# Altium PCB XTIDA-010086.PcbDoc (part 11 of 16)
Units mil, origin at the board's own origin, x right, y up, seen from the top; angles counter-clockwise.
Board outline 14763.78 x 8267.72 mil, 6 copper layers (Top Layer, GND Layer, Signal Layer 1, Signal Layer 2, Power Layer, Bottom Layer), stack 62 mil thick; 1933 components, 1002 nets, 4886 pads, 6482 vias.
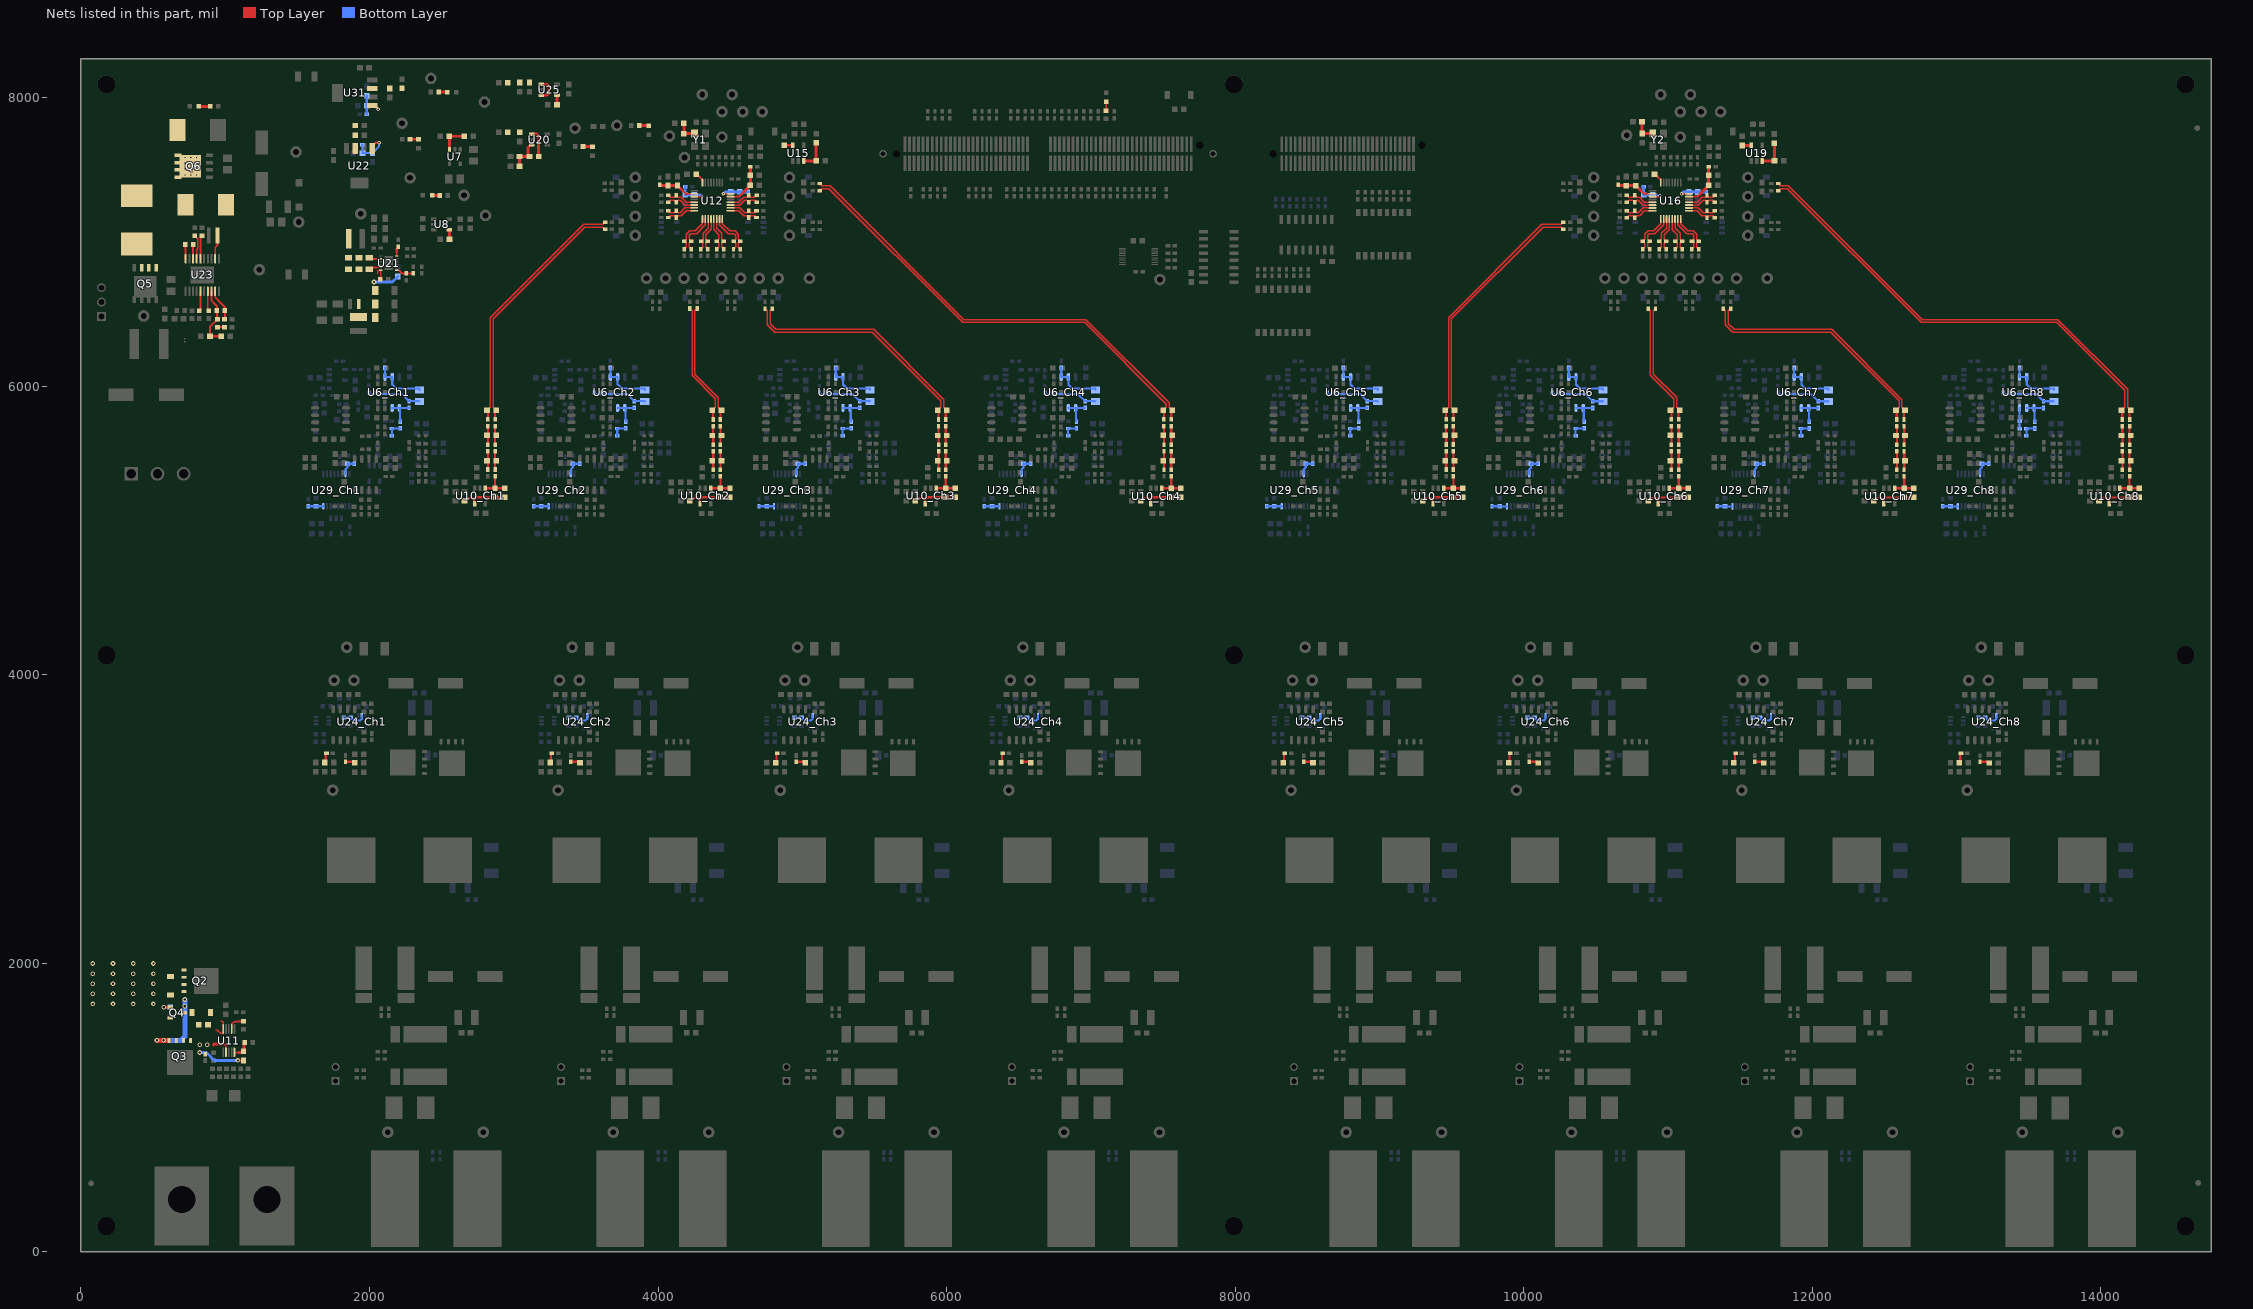
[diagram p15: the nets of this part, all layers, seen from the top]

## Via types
v1: diameter 32, hole 16, Top Layer to Bottom Layer, tented both sides, 4685 vias
v2: diameter 24, hole 12, Top Layer to Bottom Layer, tented both sides, 1013 vias
v3: diameter 32, hole 16, Top Layer to Bottom Layer, 728 vias
v4: diameter 19.68, hole 7.87, Top Layer to Bottom Layer, 40 vias
v5: diameter 214.57, hole 140, Top Layer to Bottom Layer, 16 vias

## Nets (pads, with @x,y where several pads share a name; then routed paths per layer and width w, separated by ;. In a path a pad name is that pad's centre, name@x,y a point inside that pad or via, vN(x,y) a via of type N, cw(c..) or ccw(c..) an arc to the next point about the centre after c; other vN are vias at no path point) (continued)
NetC38_Ch8_1: C38_Ch8.1 R53_Ch8.2 U6_Ch8.3 | length 142.9
  Bottom Layer w15: U6_Ch8.3@13435.7,5848.21 13436.08,5847.83 C38_Ch8.1@13436.08,5755.5 R53_Ch8.2@13436.08,5705.5
NetC41_Ch1_1: C41_Ch1.1 R50_Ch1.1 U6_Ch1.1 U6_Ch1.2 | length 213.7
  Bottom Layer w15: U6_Ch1.2@2158,5848.76 U6_Ch1.1@2208,5848.76 ; C41_Ch1.1@2214,5753.67 2211.79,5755.88 2211.79,5844.98 U6_Ch1.1@2208,5848.76 ; R50_Ch1.1@2274,5848.43 2273.66,5848.76 U6_Ch1.1@2208,5848.76
NetC41_Ch1_2: C41_Ch1.2 R52_Ch1.2 R53_Ch1.1 | length 108.5
  Bottom Layer w15: R52_Ch1.2@2155.62,5656.05 R53_Ch1.1@2155.62,5706.05 2213.62,5706.05 C41_Ch1.2@2214,5706.43
NetC41_Ch2_1: C41_Ch2.1 R50_Ch2.1 U6_Ch2.1 U6_Ch2.2 | length 213.7
  Bottom Layer w15: U6_Ch2.2@3720,5848.68 U6_Ch2.1@3770,5848.68 ; C41_Ch2.1@3776,5753.59 3773.79,5755.8 3773.79,5844.9 U6_Ch2.1@3770,5848.68 ; R50_Ch2.1@3836,5848.35 3835.66,5848.68 U6_Ch2.1@3770,5848.68
NetC41_Ch2_2: C41_Ch2.2 R52_Ch2.2 R53_Ch2.1 | length 108.5
  Bottom Layer w15: R52_Ch2.2@3717.62,5655.97 R53_Ch2.1@3717.62,5705.97 3775.62,5705.97 C41_Ch2.2@3776,5706.35
NetC41_Ch3_1: C41_Ch3.1 R50_Ch3.1 U6_Ch3.1 U6_Ch3.2 | length 213.7
  Bottom Layer w15: U6_Ch3.2@5282,5848.61 U6_Ch3.1@5332,5848.61 ; C41_Ch3.1@5338,5753.51 5335.79,5755.72 5335.79,5844.82 U6_Ch3.1@5332,5848.61 ; R50_Ch3.1@5398,5848.27 5397.66,5848.61 U6_Ch3.1@5332,5848.61
NetC41_Ch3_2: C41_Ch3.2 R52_Ch3.2 R53_Ch3.1 | length 108.5
  Bottom Layer w15: R52_Ch3.2@5279.62,5655.89 R53_Ch3.1@5279.62,5705.89 5337.62,5705.89 C41_Ch3.2@5338,5706.27
NetC41_Ch4_1: C41_Ch4.1 R50_Ch4.1 U6_Ch4.1 U6_Ch4.2 | length 213.7
  Bottom Layer w15: U6_Ch4.2@6844,5848.53 U6_Ch4.1@6894,5848.53 ; C41_Ch4.1@6900,5753.43 6897.79,5755.65 6897.79,5844.74 U6_Ch4.1@6894,5848.53 ; R50_Ch4.1@6960,5848.19 6959.66,5848.53 U6_Ch4.1@6894,5848.53
NetC41_Ch4_2: C41_Ch4.2 R52_Ch4.2 R53_Ch4.1 | length 108.5
  Bottom Layer w15: R52_Ch4.2@6841.62,5655.81 R53_Ch4.1@6841.62,5705.81 6899.62,5705.81 C41_Ch4.2@6900,5706.19
NetC41_Ch5_1: C41_Ch5.1 R50_Ch5.1 U6_Ch5.1 U6_Ch5.2 | length 213.7
  Bottom Layer w15: U6_Ch5.2@8799.7,5848.45 U6_Ch5.1@8849.7,5848.45 ; C41_Ch5.1@8855.7,5753.35 8853.49,5755.57 8853.49,5844.66 U6_Ch5.1@8849.7,5848.45 ; R50_Ch5.1@8915.7,5848.11 8915.36,5848.45 U6_Ch5.1@8849.7,5848.45
NetC41_Ch5_2: C41_Ch5.2 R52_Ch5.2 R53_Ch5.1 | length 108.5
  Bottom Layer w15: R52_Ch5.2@8797.32,5655.73 R53_Ch5.1@8797.32,5705.73 8855.32,5705.73 C41_Ch5.2@8855.7,5706.11
NetC41_Ch6_1: C41_Ch6.1 R50_Ch6.1 U6_Ch6.1 U6_Ch6.2 | length 213.7
  Bottom Layer w15: U6_Ch6.2@10361.7,5848.37 U6_Ch6.1@10411.7,5848.37 ; C41_Ch6.1@10417.7,5753.28 10415.49,5755.49 10415.49,5844.58 U6_Ch6.1@10411.7,5848.37 ; R50_Ch6.1@10477.7,5848.03 10477.36,5848.37 U6_Ch6.1@10411.7,5848.37
NetC41_Ch6_2: C41_Ch6.2 R52_Ch6.2 R53_Ch6.1 | length 108.5
  Bottom Layer w15: R52_Ch6.2@10359.32,5655.65 R53_Ch6.1@10359.32,5705.65 10417.32,5705.65 C41_Ch6.2@10417.7,5706.03
NetC41_Ch7_1: C41_Ch7.1 R50_Ch7.1 U6_Ch7.1 U6_Ch7.2 | length 213.7
  Bottom Layer w15: U6_Ch7.2@11923.7,5848.29 U6_Ch7.1@11973.7,5848.29 ; C41_Ch7.1@11979.7,5753.2 11977.49,5755.41 11977.49,5844.5 U6_Ch7.1@11973.7,5848.29 ; R50_Ch7.1@12039.7,5847.95 12039.36,5848.29 U6_Ch7.1@11973.7,5848.29
NetC41_Ch7_2: C41_Ch7.2 R52_Ch7.2 R53_Ch7.1 | length 108.5
  Bottom Layer w15: R52_Ch7.2@11921.32,5655.57 R53_Ch7.1@11921.32,5705.57 11979.32,5705.57 C41_Ch7.2@11979.7,5705.95
NetC41_Ch8_1: C41_Ch8.1 R50_Ch8.1 U6_Ch8.1 U6_Ch8.2 | length 213.7
  Bottom Layer w15: U6_Ch8.2@13485.7,5848.21 U6_Ch8.1@13535.7,5848.21 ; C41_Ch8.1@13541.7,5753.12 13539.49,5755.33 13539.49,5844.43 U6_Ch8.1@13535.7,5848.21 ; R50_Ch8.1@13601.7,5847.87 13601.36,5848.21 U6_Ch8.1@13535.7,5848.21
NetC41_Ch8_2: C41_Ch8.2 R52_Ch8.2 R53_Ch8.1 | length 108.5
  Bottom Layer w15: R52_Ch8.2@13483.32,5655.5 R53_Ch8.1@13483.32,5705.5 13541.32,5705.5 C41_Ch8.2@13541.7,5705.87
NetC42_Ch1_1: C42_Ch1.1 R186_Ch1.1 U6_Ch1.6 U6_Ch1.7 | length 376.8
  Bottom Layer w15: R186_Ch1.1@2107,6127.76 2108,6126.76 U6_Ch1.6@2108,6063.33 U6_Ch1.7@2158,6063.33 2158,6011.49 2185.79,5983.7 2346,5983.7 C42_Ch1.1@2346,5973.05
NetC42_Ch1_2: C42_Ch1.2 R50_Ch1.2 R51_Ch1.1 | length 375.9
  Bottom Layer w15: R51_Ch1.1@1995,5953.05 2002.35,5945.7 2223.97,5945.7 R50_Ch1.2@2274,5895.67 2343.38,5895.67 C42_Ch1.2@2346,5893.05
NetC42_Ch2_1: C42_Ch2.1 R186_Ch2.1 U6_Ch2.6 U6_Ch2.7 | length 375.4
  Bottom Layer w15: R186_Ch2.1@3670,6126.68 U6_Ch2.6@3670,6063.25 U6_Ch2.7@3720,6063.25 3720,6011.41 3747.79,5983.62 3908,5983.62 C42_Ch2.1@3908,5972.97
NetC42_Ch2_2: C42_Ch2.2 R50_Ch2.2 R51_Ch2.1 | length 375.9
  Bottom Layer w15: R51_Ch2.1@3557,5952.97 3564.35,5945.62 3785.97,5945.62 R50_Ch2.2@3836,5895.59 3905.38,5895.59 C42_Ch2.2@3908,5892.97
NetC42_Ch3_1: C42_Ch3.1 R186_Ch3.1 U6_Ch3.6 U6_Ch3.7 | length 375.4
  Bottom Layer w15: R186_Ch3.1@5232,6126.6 U6_Ch3.6@5232,6063.17 U6_Ch3.7@5282,6063.17 5282,6011.33 5309.79,5983.54 5470,5983.54 C42_Ch3.1@5470,5972.89
NetC42_Ch3_2: C42_Ch3.2 R50_Ch3.2 R51_Ch3.1 | length 375.9
  Bottom Layer w15: R51_Ch3.1@5119,5952.89 5126.35,5945.54 5347.97,5945.54 R50_Ch3.2@5398,5895.51 5467.38,5895.51 C42_Ch3.2@5470,5892.89
NetC42_Ch4_1: C42_Ch4.1 R186_Ch4.1 U6_Ch4.6 U6_Ch4.7 | length 375.4
  Bottom Layer w15: R186_Ch4.1@6794,6126.52 U6_Ch4.6@6794,6063.09 U6_Ch4.7@6844,6063.09 6844,6011.25 6871.79,5983.46 7032,5983.46 C42_Ch4.1@7032,5972.81
NetC42_Ch4_2: C42_Ch4.2 R50_Ch4.2 R51_Ch4.1 | length 375.9
  Bottom Layer w15: R51_Ch4.1@6681,5952.81 6688.35,5945.46 6909.97,5945.46 R50_Ch4.2@6960,5895.43 7029.38,5895.43 C42_Ch4.2@7032,5892.81
NetC42_Ch5_1: C42_Ch5.1 R186_Ch5.1 U6_Ch5.6 U6_Ch5.7 | length 375.4
  Bottom Layer w15: R186_Ch5.1@8749.7,6126.44 U6_Ch5.6@8749.7,6063.02 U6_Ch5.7@8799.7,6063.02 8799.7,6011.17 8827.49,5983.39 8987.7,5983.39 C42_Ch5.1@8987.7,5972.73
NetC42_Ch5_2: C42_Ch5.2 R50_Ch5.2 R51_Ch5.1 | length 375.9
  Bottom Layer w15: R51_Ch5.1@8636.7,5952.73 8644.05,5945.39 8865.67,5945.39 R50_Ch5.2@8915.7,5895.35 8985.08,5895.35 C42_Ch5.2@8987.7,5892.73
NetC42_Ch6_1: C42_Ch6.1 R186_Ch6.1 U6_Ch6.6 U6_Ch6.7 | length 375.4
  Bottom Layer w15: R186_Ch6.1@10311.7,6126.36 U6_Ch6.6@10311.7,6062.94 U6_Ch6.7@10361.7,6062.94 10361.7,6011.09 10389.49,5983.31 10549.7,5983.31 C42_Ch6.1@10549.7,5972.65
NetC42_Ch6_2: C42_Ch6.2 R50_Ch6.2 R51_Ch6.1 | length 375.9
  Bottom Layer w15: R51_Ch6.1@10198.7,5952.65 10206.05,5945.31 10427.67,5945.31 R50_Ch6.2@10477.7,5895.28 10547.08,5895.28 C42_Ch6.2@10549.7,5892.65
NetC42_Ch7_1: C42_Ch7.1 R186_Ch7.1 U6_Ch7.6 U6_Ch7.7 | length 375.4
  Bottom Layer w15: R186_Ch7.1@11873.7,6126.28 U6_Ch7.6@11873.7,6062.86 U6_Ch7.7@11923.7,6062.86 11923.7,6011.02 11951.49,5983.23 12111.7,5983.23 C42_Ch7.1@12111.7,5972.57
NetC42_Ch7_2: C42_Ch7.2 R50_Ch7.2 R51_Ch7.1 | length 375.9
  Bottom Layer w15: R51_Ch7.1@11760.7,5952.57 11768.05,5945.23 11989.67,5945.23 R50_Ch7.2@12039.7,5895.2 12109.08,5895.2 C42_Ch7.2@12111.7,5892.57
NetC42_Ch8_1: C42_Ch8.1 R186_Ch8.1 U6_Ch8.6 U6_Ch8.7 | length 375.4
  Bottom Layer w15: R186_Ch8.1@13435.7,6126.2 U6_Ch8.6@13435.7,6062.78 U6_Ch8.7@13485.7,6062.78 13485.7,6010.94 13513.49,5983.15 13673.7,5983.15 C42_Ch8.1@13673.7,5972.5
NetC42_Ch8_2: C42_Ch8.2 R50_Ch8.2 R51_Ch8.1 | length 375.9
  Bottom Layer w15: R51_Ch8.1@13322.7,5952.5 13330.05,5945.15 13551.67,5945.15 R50_Ch8.2@13601.7,5895.12 13671.08,5895.12 C42_Ch8.2@13673.7,5892.5
NetC48_Ch1_1: C48_Ch1.1 R65_Ch1.2 R66_Ch1.1 | length 131.7
  Top Layer w15: R65_Ch1.2@2871,5421.7 2871,5474.93 C48_Ch1.1@2878.15,5482.08 2871,5489.23 R66_Ch1.1@2871,5547.46
NetC48_Ch1_2: C48_Ch1.2 R71_Ch1.2 R72_Ch1.1 | length 130.6
  Top Layer w15: R71_Ch1.2@2821,5421.7 2821,5476.24 C48_Ch1.2@2815.16,5482.08 2821,5487.92 R72_Ch1.1@2821,5547.46
NetC48_Ch2_1: C48_Ch2.1 R65_Ch2.2 R66_Ch2.1 | length 131.7
  Top Layer w15: R65_Ch2.2@4432.54,5421.17 4432.54,5474.39 C48_Ch2.1@4439.69,5481.54 4432.54,5488.69 R66_Ch2.1@4432.54,5546.92
NetC48_Ch2_2: C48_Ch2.2 R71_Ch2.2 R72_Ch2.1 | length 130.6
  Top Layer w15: R71_Ch2.2@4382.54,5421.17 4382.54,5475.7 C48_Ch2.2@4376.7,5481.54 4382.54,5487.39 R72_Ch2.1@4382.54,5546.92
NetC48_Ch3_1: C48_Ch3.1 R65_Ch3.2 R66_Ch3.1 | length 131.7
  Top Layer w15: R65_Ch3.2@5994.54,5421.09 5994.54,5474.32 C48_Ch3.1@6001.69,5481.46 5994.54,5488.61 R66_Ch3.1@5994.54,5546.84
NetC48_Ch3_2: C48_Ch3.2 R71_Ch3.2 R72_Ch3.1 | length 130.6
  Top Layer w15: R71_Ch3.2@5944.54,5421.09 5944.54,5475.62 C48_Ch3.2@5938.7,5481.46 5944.54,5487.31 R72_Ch3.1@5944.54,5546.84
NetC48_Ch4_1: C48_Ch4.1 R65_Ch4.2 R66_Ch4.1 | length 131.7
  Top Layer w15: R65_Ch4.2@7556.54,5421.01 7556.54,5474.24 7563.69,5481.39 7556.54,5488.53 R66_Ch4.1@7556.54,5546.76
NetC48_Ch4_2: C48_Ch4.2 R71_Ch4.2 R72_Ch4.1 | length 130.6
  Top Layer w15: R71_Ch4.2@7506.54,5421.01 7506.54,5475.54 7500.7,5481.39 7506.54,5487.23 R72_Ch4.1@7506.54,5546.76
NetC48_Ch5_1: C48_Ch5.1 R65_Ch5.2 R66_Ch5.1 | length 131.7
  Top Layer w15: R65_Ch5.2@9512.24,5420.93 9512.24,5474.16 9519.39,5481.31 9512.24,5488.46 R66_Ch5.1@9512.24,5546.69
NetC48_Ch5_2: C48_Ch5.2 R71_Ch5.2 R72_Ch5.1 | length 130.6
  Top Layer w15: R71_Ch5.2@9462.24,5420.93 9462.24,5475.46 9456.4,5481.31 9462.24,5487.15 R72_Ch5.1@9462.24,5546.69
NetC48_Ch6_1: C48_Ch6.1 R65_Ch6.2 R66_Ch6.1 | length 131.7
  Top Layer w15: R65_Ch6.2@11074.24,5420.85 11074.24,5474.08 11081.39,5481.23 11074.24,5488.38 R66_Ch6.1@11074.24,5546.61
NetC48_Ch6_2: C48_Ch6.2 R71_Ch6.2 R72_Ch6.1 | length 130.6
  Top Layer w15: R71_Ch6.2@11024.24,5420.85 11024.24,5475.38 11018.4,5481.23 11024.24,5487.07 R72_Ch6.1@11024.24,5546.61
NetC48_Ch7_1: C48_Ch7.1 R65_Ch7.2 R66_Ch7.1 | length 131.7
  Top Layer w15: R65_Ch7.2@12636.24,5420.77 12636.24,5474 12643.39,5481.15 12636.24,5488.3 R66_Ch7.1@12636.24,5546.53
NetC48_Ch7_2: C48_Ch7.2 R71_Ch7.2 R72_Ch7.1 | length 130.6
  Top Layer w15: R71_Ch7.2@12586.24,5420.77 12586.24,5475.31 12580.4,5481.15 12586.24,5486.99 R72_Ch7.1@12586.24,5546.53
NetC48_Ch8_1: C48_Ch8.1 R65_Ch8.2 R66_Ch8.1 | length 131.7
  Top Layer w15: R65_Ch8.2@14198.24,5420.69 14198.24,5473.92 14205.39,5481.07 14198.24,5488.22 R66_Ch8.1@14198.24,5546.45
NetC48_Ch8_2: C48_Ch8.2 R71_Ch8.2 R72_Ch8.1 | length 130.6
  Top Layer w15: R71_Ch8.2@14148.24,5420.69 14148.24,5475.23 14142.4,5481.07 14148.24,5486.91 R72_Ch8.1@14148.24,5546.45
NetC49_Ch1_1: C49_Ch1.1 R66_Ch1.2 R67_Ch1.1 | length 132.7
  Top Layer w15: R66_Ch1.2@2871,5594.7 2871,5650.93 C49_Ch1.1@2878.15,5658.08 2871,5665.23 R67_Ch1.1@2871,5721.46
NetC49_Ch1_2: C49_Ch1.2 R72_Ch1.2 R73_Ch1.1 | length 131.6
  Top Layer w15: R72_Ch1.2@2821,5594.7 2821,5652.24 C49_Ch1.2@2815.16,5658.08 2821,5663.92 R73_Ch1.1@2821,5721.46
NetC49_Ch2_1: C49_Ch2.1 R66_Ch2.2 R67_Ch2.1 | length 132.7
  Top Layer w15: R66_Ch2.2@4432.54,5594.17 4432.54,5650.39 C49_Ch2.1@4439.69,5657.54 4432.54,5664.69 R67_Ch2.1@4432.54,5720.92
NetC49_Ch2_2: C49_Ch2.2 R72_Ch2.2 R73_Ch2.1 | length 131.4
  Top Layer w15: R73_Ch2.1@4382.09,5720.92 4382.09,5662.93 C49_Ch2.2@4376.7,5657.54 4382.54,5651.7 R72_Ch2.2@4382.54,5594.17
NetC49_Ch3_1: C49_Ch3.1 R66_Ch3.2 R67_Ch3.1 | length 132.7
  Top Layer w15: R66_Ch3.2@5994.54,5594.09 5994.54,5650.32 C49_Ch3.1@6001.69,5657.46 5994.54,5664.61 R67_Ch3.1@5994.54,5720.84
NetC49_Ch3_2: C49_Ch3.2 R72_Ch3.2 R73_Ch3.1 | length 131.4
  Top Layer w15: R73_Ch3.1@5944.09,5720.84 5944.09,5662.85 C49_Ch3.2@5938.7,5657.46 5944.54,5651.62 R72_Ch3.2@5944.54,5594.09
NetC49_Ch4_1: C49_Ch4.1 R66_Ch4.2 R67_Ch4.1 | length 132.7
  Top Layer w15: R66_Ch4.2@7556.54,5594.01 7556.54,5650.24 7563.69,5657.39 7556.54,5664.53 R67_Ch4.1@7556.54,5720.76
NetC49_Ch4_2: C49_Ch4.2 R72_Ch4.2 R73_Ch4.1 | length 131.4
  Top Layer w15: R73_Ch4.1@7506.09,5720.76 7506.09,5662.77 7500.7,5657.39 7506.54,5651.54 R72_Ch4.2@7506.54,5594.01
NetC49_Ch5_1: C49_Ch5.1 R66_Ch5.2 R67_Ch5.1 | length 132.7
  Top Layer w15: R66_Ch5.2@9512.24,5593.93 9512.24,5650.16 9519.39,5657.31 9512.24,5664.46 R67_Ch5.1@9512.24,5720.69
NetC49_Ch5_2: C49_Ch5.2 R72_Ch5.2 R73_Ch5.1 | length 131.4
  Top Layer w15: R73_Ch5.1@9461.79,5720.69 9461.79,5662.69 9456.4,5657.31 9462.24,5651.46 R72_Ch5.2@9462.24,5593.93
NetC49_Ch6_1: C49_Ch6.1 R66_Ch6.2 R67_Ch6.1 | length 132.7
  Top Layer w15: R66_Ch6.2@11074.24,5593.85 11074.24,5650.08 11081.39,5657.23 11074.24,5664.38 R67_Ch6.1@11074.24,5720.61
NetC49_Ch6_2: C49_Ch6.2 R72_Ch6.2 R73_Ch6.1 | length 131.4
  Top Layer w15: R73_Ch6.1@11023.79,5720.61 11023.79,5662.62 11018.4,5657.23 11024.24,5651.38 R72_Ch6.2@11024.24,5593.85
NetC49_Ch7_1: C49_Ch7.1 R66_Ch7.2 R67_Ch7.1 | length 132.7
  Top Layer w15: R66_Ch7.2@12636.24,5593.77 12636.24,5650 12643.39,5657.15 12636.24,5664.3 R67_Ch7.1@12636.24,5720.53
NetC49_Ch7_2: C49_Ch7.2 R72_Ch7.2 R73_Ch7.1 | length 131.4
  Top Layer w15: R73_Ch7.1@12585.79,5720.53 12585.79,5662.54 12580.4,5657.15 12586.24,5651.31 R72_Ch7.2@12586.24,5593.77
NetC49_Ch8_1: C49_Ch8.1 R66_Ch8.2 R67_Ch8.1 | length 132.7
  Top Layer w15: R66_Ch8.2@14198.24,5593.69 14198.24,5649.92 14205.39,5657.07 14198.24,5664.22 R67_Ch8.1@14198.24,5720.45
NetC49_Ch8_2: C49_Ch8.2 R72_Ch8.2 R73_Ch8.1 | length 131.4
  Top Layer w15: R73_Ch8.1@14147.79,5720.45 14147.79,5662.46 14142.4,5657.07 14148.24,5651.23 R72_Ch8.2@14148.24,5593.69
NetC50_Ch1_1: C50_Ch1.1 R67_Ch1.2 R68_Ch1.1 | length 1754.7
  Top Layer w10: C50_Ch1.1@2878.15,5832.08 2856.65,5853.57 2856.65,6465.35 3492.21,7100.91 3618,7100.91 R68_Ch1.1@3633.23,7085.68
  Top Layer w15: R67_Ch1.2@2871,5768.7 2871,5824.93 C50_Ch1.1@2878.15,5832.08
NetC50_Ch1_2: C50_Ch1.2 R73_Ch1.2 R74_Ch1.1 | length 1787.3
  Top Layer w10: C50_Ch1.2@2815.16,5832.08 2836.65,5853.57 2836.65,6473.64 3483.92,7120.91 3618,7120.91 R74_Ch1.1@3633.23,7136.14
  Top Layer w15: C50_Ch1.2@2815.16,5832.08 2821,5826.24 R73_Ch1.2@2821,5768.7
NetC50_Ch2_1: C50_Ch2.1 R67_Ch2.2 R68_Ch2.1 | length 854.7
  Top Layer w10: R68_Ch2.1@4271.03,6537.4 4255.8,6522.17 4255.8,6082.9 4418.2,5920.5 4418.2,5853.04 C50_Ch2.1@4439.69,5831.54
  Top Layer w15: R67_Ch2.2@4432.54,5768.17 4432.54,5824.39 C50_Ch2.1@4439.69,5831.54
NetC50_Ch2_2: C50_Ch2.2 R73_Ch2.2 R74_Ch2.1 | length 853.9
  Top Layer w10: R74_Ch2.1@4220.57,6537.4 4235.8,6522.17 4235.8,6074.62 4398.2,5912.22 4398.2,5853.04 C50_Ch2.2@4376.7,5831.54
  Top Layer w15: C50_Ch2.2@4376.7,5831.54 4382.09,5826.16 R73_Ch2.2@4382.09,5768.17
NetC50_Ch3_1: C50_Ch3.1 R67_Ch3.2 R68_Ch3.1 | length 1681.4
  Top Layer w10: R68_Ch3.1@4791.7,6536.47 4776.47,6521.24 4776.47,6433.23 4817,6392.7 5493.5,6392.7 5980.2,5906 5980.2,5852.96 C50_Ch3.1@6001.69,5831.46
  Top Layer w15: R67_Ch3.2@5994.54,5768.09 5994.54,5824.32 C50_Ch3.1@6001.69,5831.46
NetC50_Ch3_2: C50_Ch3.2 R73_Ch3.2 R74_Ch3.1 | length 1680.7
  Top Layer w10: R74_Ch3.1@4741.24,6536.47 4756.47,6521.24 4756.47,6424.95 4808.72,6372.7 5485.21,6372.7 5960.2,5897.72 5960.2,5852.96 C50_Ch3.2@5938.7,5831.46
  Top Layer w15: C50_Ch3.2@5938.7,5831.46 5944.09,5826.08 R73_Ch3.2@5944.09,5768.09
NetC50_Ch4_1: C50_Ch4.1 R67_Ch4.2 R68_Ch4.1 | length 3178.2
  Top Layer w10: R68_Ch4.1@5120.62,7403.98 5135.85,7388.75 5191.95,7388.75 6120,6460.7 6965,6460.7 7542.25,5883.45 7542.25,5853.43 C50_Ch4.1@7563.75,5831.93
  Top Layer w15: R67_Ch4.2@7556.54,5768.01 7556.54,5824.24 C50_Ch4.1@7563.69,5831.39
NetC50_Ch4_2: C50_Ch4.2 R73_Ch4.2 R74_Ch4.1 | length 3144.3
  Top Layer w10: R74_Ch4.1@5120.62,7353.52 5135.85,7368.75 5183.66,7368.75 6111.72,6440.7 6956.72,6440.7 7522.25,5875.17 7522.25,5853.43 C50_Ch4.2@7500.75,5831.93
  Top Layer w15: C50_Ch4.2@7500.7,5831.39 7506.09,5826 R73_Ch4.2@7506.09,5768.01
NetC50_Ch5_1: C50_Ch5.1 R67_Ch5.2 R68_Ch5.1 | length 1764.8
  Top Layer w10: C50_Ch5.1@9519.85,5831.76 9498.35,5853.26 9498.35,6465.04 10133.91,7100.59 10259.7,7100.59 R68_Ch5.1@10274.93,7085.37
  Top Layer w15: R67_Ch5.2@9512.24,5767.93 9512.24,5824.16 C50_Ch5.1@9519.39,5831.31 ; C50_Ch5.1@9512.7,5824.62 C50_Ch5.1@9519.85,5831.76
NetC50_Ch5_2: C50_Ch5.2 R73_Ch5.2 R74_Ch5.1 | length 1795.3
  Top Layer w10: C50_Ch5.2@9456.86,5831.76 9478.35,5853.26 9478.35,6473.32 10125.62,7120.59 10259.7,7120.59 R74_Ch5.1@10274.93,7135.82
  Top Layer w15: C50_Ch5.2@9456.4,5831.31 9461.79,5825.92 R73_Ch5.2@9461.79,5767.93 ; C50_Ch5.2@9456.86,5831.76 C50_Ch5.2@9462.7,5825.92
NetC50_Ch6_1: C50_Ch6.1 R67_Ch6.2 R68_Ch6.1 | length 854.7
  Top Layer w10: R68_Ch6.1@10911.78,6537.63 10896.56,6522.4 10896.56,6083.13 11058.95,5920.73 11058.95,5853.27 C50_Ch6.1@11080.45,5831.77
  Top Layer w15: R67_Ch6.2@11073.3,5768.4 11073.3,5824.62 C50_Ch6.1@11080.45,5831.77
NetC50_Ch6_2: C50_Ch6.2 R73_Ch6.2 R74_Ch6.1 | length 853.9
  Top Layer w10: R74_Ch6.1@10861.33,6537.63 10876.56,6522.4 10876.56,6074.85 11038.95,5912.45 11038.95,5853.27 C50_Ch6.2@11017.45,5831.77
  Top Layer w15: C50_Ch6.2@11017.45,5831.77 11022.84,5826.39 R73_Ch6.2@11022.84,5768.4
NetC50_Ch7_1: C50_Ch7.1 R67_Ch7.2 R68_Ch7.1 | length 1691.5
  Top Layer w10: R68_Ch7.1@11432.45,6536.7 11417.23,6521.47 11417.23,6433.46 11457.75,6392.93 12134.25,6392.93 12620.95,5906.23 12620.95,5853.19 C50_Ch7.1@12642.45,5831.69
  Top Layer w15: R67_Ch7.2@12635.3,5768.32 12635.3,5824.55 C50_Ch7.1@12642.45,5831.69 ; C50_Ch7.1@12636.24,5824 C50_Ch7.1@12643.39,5831.15
NetC50_Ch7_2: C50_Ch7.2 R73_Ch7.2 R74_Ch7.1 | length 1688.3
  Top Layer w10: R74_Ch7.1@11382,6536.7 11397.23,6521.47 11397.23,6425.18 11449.47,6372.93 12125.97,6372.93 12600.95,5897.95 12600.95,5853.19 C50_Ch7.2@12579.45,5831.69
  Top Layer w15: C50_Ch7.2@12579.45,5831.69 12584.84,5826.31 R73_Ch7.2@12584.84,5768.32 ; C50_Ch7.2@12580.4,5831.15 C50_Ch7.2@12585.79,5825.76
NetC50_Ch8_1: C50_Ch8.1 R67_Ch8.2 R68_Ch8.1 | length 3233.4
  Top Layer w10: R68_Ch8.1@11762.38,7404.21 11777.61,7388.98 11833.7,7388.98 12761.75,6460.93 13701.04,6460.93 14184,5977.96 14184,5853.66 C50_Ch8.1@14205.5,5832.16
  Top Layer w15: R67_Ch8.2@14198.3,5768.24 14198.3,5824.47 C50_Ch8.1@14205.45,5831.62
NetC50_Ch8_2: C50_Ch8.2 R73_Ch8.2 R74_Ch8.1 | length 3199.6
  Top Layer w10: R74_Ch8.1@11762.38,7353.75 11777.61,7368.98 11825.42,7368.98 12753.47,6440.93 13692.75,6440.93 14164,5969.68 14164,5853.66 C50_Ch8.2@14142.51,5832.16
  Top Layer w15: C50_Ch8.2@14142.45,5831.62 14147.84,5826.23 R73_Ch8.2@14147.84,5768.24
NetC54_Ch1_1: C54_Ch1.1 R70_Ch1.2 R77_Ch1.1 U10_Ch1.4 | length 326.3
  Top Layer w15: R70_Ch1.2@2659.04,5204.3 2679.66,5224.92 2715.9,5224.92 2729.14,5211.69 ; U10_Ch1.4@2729.14,5184.17 2729.14,5211.69 ; R77_Ch1.1@2936.54,5229.18 C54_Ch1.1@2870.54,5229.18 2746.64,5229.18 2729.14,5211.69
NetC54_Ch1_2: C54_Ch1.2 R65_Ch1.1 R77_Ch1.2 U10_Ch1.1 | length 219.9
  Top Layer w15: U10_Ch1.1@2807.25,5295.74 U10_Ch1.1@2803.94,5292.43 2804.2,5292.17 C54_Ch1.2@2870.54,5292.17 ; R65_Ch1.1@2871,5374.46 2870.54,5374 C54_Ch1.2@2870.54,5292.17 ; R77_Ch1.2@2936.54,5292.17 C54_Ch1.2@2870.54,5292.17
NetC54_Ch2_1: C54_Ch2.1 R70_Ch2.2 R77_Ch2.1 U10_Ch2.4 | length 326.3
  Top Layer w15: R70_Ch2.2@4221.04,5204.22 4241.66,5224.84 4277.9,5224.84 4291.14,5211.61 ; U10_Ch2.4@4291.14,5184.09 4291.14,5211.61 ; R77_Ch2.1@4498.54,5229.1 C54_Ch2.1@4432.54,5229.1 4308.64,5229.1 4291.14,5211.61
NetC54_Ch2_2: C54_Ch2.2 R65_Ch2.1 R77_Ch2.2 U10_Ch2.1 | length 219.2
  Top Layer w15: U10_Ch2.1@4369.25,5295.66 U10_Ch2.1@4365.94,5292.35 4366.2,5292.09 C54_Ch2.2@4432.54,5292.09 ; R65_Ch2.1@4432.54,5373.92 C54_Ch2.2@4432.54,5292.09 ; R77_Ch2.2@4498.54,5292.09 C54_Ch2.2@4432.54,5292.09
NetC54_Ch3_1: C54_Ch3.1 R70_Ch3.2 R77_Ch3.1 U10_Ch3.4 | length 326.3
  Top Layer w15: R70_Ch3.2@5783.04,5204.14 5803.66,5224.77 5839.9,5224.77 5853.14,5211.53 ; U10_Ch3.4@5853.14,5184.01 5853.14,5211.53 ; R77_Ch3.1@6060.54,5229.02 C54_Ch3.1@5994.54,5229.02 5870.64,5229.02 5853.14,5211.53
NetC54_Ch3_2: C54_Ch3.2 R65_Ch3.1 R77_Ch3.2 U10_Ch3.1 | length 219.2
  Top Layer w15: U10_Ch3.1@5931.25,5295.58 U10_Ch3.1@5927.94,5292.28 5928.2,5292.02 C54_Ch3.2@5994.54,5292.02 ; R65_Ch3.1@5994.54,5373.84 C54_Ch3.2@5994.54,5292.02 ; R77_Ch3.2@6060.54,5292.02 C54_Ch3.2@5994.54,5292.02
NetC54_Ch4_1: C54_Ch4.1 R70_Ch4.2 R77_Ch4.1 U10_Ch4.4 | length 326.3
  Top Layer w15: R70_Ch4.2@7345.04,5204.06 7365.66,5224.69 7401.9,5224.69 7415.14,5211.45 ; U10_Ch4.4@7415.14,5183.93 7415.14,5211.45 ; R77_Ch4.1@7622.54,5228.94 C54_Ch4.1@7556.54,5228.94 7432.64,5228.94 7415.14,5211.45
NetC54_Ch4_2: C54_Ch4.2 R65_Ch4.1 R77_Ch4.2 U10_Ch4.1 | length 219.2
  Top Layer w15: U10_Ch4.1@7493.25,5295.5 U10_Ch4.1@7489.94,5292.2 7490.2,5291.94 C54_Ch4.2@7556.54,5291.94 ; R65_Ch4.1@7556.54,5373.76 C54_Ch4.2@7556.54,5291.94 ; R77_Ch4.2@7622.54,5291.94 C54_Ch4.2@7556.54,5291.94
NetC54_Ch5_1: C54_Ch5.1 R70_Ch5.2 R77_Ch5.1 U10_Ch5.4 | length 326.3
  Top Layer w15: R70_Ch5.2@9300.74,5203.98 9321.36,5224.61 9357.6,5224.61 9370.84,5211.37 ; U10_Ch5.4@9370.84,5183.85 9370.84,5211.37 ; R77_Ch5.1@9578.24,5228.87 C54_Ch5.1@9512.24,5228.87 9388.34,5228.87 9370.84,5211.37
NetC54_Ch5_2: C54_Ch5.2 R65_Ch5.1 R77_Ch5.2 U10_Ch5.1 | length 214.2
  Top Layer w15: U10_Ch5.1@9445.91,5291.86 C54_Ch5.2@9512.24,5291.86 ; R65_Ch5.1@9512.24,5373.69 C54_Ch5.2@9512.24,5291.86 ; R77_Ch5.2@9578.24,5291.86 C54_Ch5.2@9512.24,5291.86
NetC54_Ch6_1: C54_Ch6.1 R70_Ch6.2 R77_Ch6.1 U10_Ch6.4 | length 326.3
  Top Layer w15: R70_Ch6.2@10862.74,5203.91 10883.36,5224.53 10919.6,5224.53 10932.84,5211.29 ; U10_Ch6.4@10932.84,5183.77 10932.84,5211.29 ; R77_Ch6.1@11140.24,5228.79 C54_Ch6.1@11074.24,5228.79 10950.34,5228.79 10932.84,5211.29
NetC54_Ch6_2: C54_Ch6.2 R65_Ch6.1 R77_Ch6.2 U10_Ch6.1 | length 214.2
  Top Layer w15: U10_Ch6.1@11007.91,5291.78 C54_Ch6.2@11074.24,5291.78 ; R65_Ch6.1@11074.24,5373.61 C54_Ch6.2@11074.24,5291.78 ; R77_Ch6.2@11140.24,5291.78 C54_Ch6.2@11074.24,5291.78
NetC54_Ch7_1: C54_Ch7.1 R70_Ch7.2 R77_Ch7.1 U10_Ch7.4 | length 326.3
  Top Layer w15: R70_Ch7.2@12424.74,5203.83 12445.36,5224.45 12481.6,5224.45 12494.84,5211.21 ; U10_Ch7.4@12494.84,5183.69 12494.84,5211.21 ; R77_Ch7.1@12702.24,5228.71 C54_Ch7.1@12636.24,5228.71 12512.34,5228.71 12494.84,5211.21
NetC54_Ch7_2: C54_Ch7.2 R65_Ch7.1 R77_Ch7.2 U10_Ch7.1 | length 219.2
  Top Layer w15: U10_Ch7.1@12572.95,5295.27 U10_Ch7.1@12569.65,5291.96 12569.91,5291.7 C54_Ch7.2@12636.24,5291.7 ; R65_Ch7.1@12636.24,5373.53 C54_Ch7.2@12636.24,5291.7 ; R77_Ch7.2@12702.24,5291.7 C54_Ch7.2@12636.24,5291.7
NetC54_Ch8_1: C54_Ch8.1 R70_Ch8.2 R77_Ch8.1 U10_Ch8.4 | length 326.3
  Top Layer w15: R70_Ch8.2@13986.74,5203.75 14007.36,5224.37 14043.6,5224.37 14056.84,5211.13 ; U10_Ch8.4@14056.84,5183.61 14056.84,5211.13 ; R77_Ch8.1@14264.24,5228.63 C54_Ch8.1@14198.24,5228.63 14074.34,5228.63 14056.84,5211.13
NetC54_Ch8_2: C54_Ch8.2 R65_Ch8.1 R77_Ch8.2 U10_Ch8.1 | length 219.2
  Top Layer w15: U10_Ch8.1@14134.95,5295.19 U10_Ch8.1@14131.65,5291.88 14131.91,5291.62 C54_Ch8.2@14198.24,5291.62 ; R65_Ch8.1@14198.24,5373.45 C54_Ch8.2@14198.24,5291.62 ; R77_Ch8.2@14264.24,5291.62 C54_Ch8.2@14198.24,5291.62
NetC56_2: C56.2 U11.7 | length 125.1
  Top Layer w10: U11.7@1045.02,1544.48 1045.02,1573.02 1045.92,1573.92 1045.92,1579.82 1062.1,1596 1079,1596
  Top Layer w15: 1079,1596 1124.21,1596 C56.2@1127.33,1599.12
NetC58_1: C58.1 R87.1 U11.5 | length 128.6
  Top Layer w10: U11.5@1064.7,1383.07 1066.65,1381.12 1093,1381.12
  Top Layer w20: 1093,1381.12 R87.1@1127.33,1381.12 ; R87.1@1127,1389.5 1132,1394.5 1132,1445.55 C58.1@1136.94,1450.5
NetC60_1: C60.1 R90.2 U12.29 | length 211.1
  Top Layer w10: R90.2@4070.74,7321.13 4084.36,7307.51 4112.49,7307.51 C60.1@4126.11,7321.13 4139.74,7307.51 4161.28,7307.51 4194.47,7274.33 4218.41,7274.33 4218.57,7274.17 U12.29@4251.13,7274.17
NetC60_2: C60.2 R91.2 U12.30 | length 211.5
  Top Layer w10: R91.2@4070.74,7272.95 4085.3,7287.51 4112.49,7287.51 C60.2@4126.11,7273.89 4139.74,7287.51 4153,7287.51 4186.19,7254.33 4218.41,7254.33 4218.57,7254.48 U12.30@4251.13,7254.48
NetC61_1: C61.1 R92.2 U12.31 | length 211.5
  Top Layer w10: R92.2@4070.74,7216.33 4085.3,7201.77 4112.49,7201.77 C61.1@4126.11,7215.39 4139.74,7201.77 4153,7201.77 4186.19,7234.96 4218.41,7234.96 4218.57,7234.8 U12.31@4251.13,7234.8
NetC61_2: C61.2 R93.2 U12.32 | length 211.1
  Top Layer w10: R93.2@4070.74,7168.15 4084.36,7181.77 4112.49,7181.77 C61.2@4126.11,7168.15 4139.74,7181.77 4161.28,7181.77 4194.47,7214.96 4218.41,7214.96 4218.57,7215.11 U12.32@4251.13,7215.11
NetC62_2: C62.2 U12.24 | length 79.7
  Top Layer w10: 4290.6,7446.63 4308.22,7429.02 U12.24@4308.22,7410
  Top Layer w15: C62.2@4264.11,7469.01 4268.22,7469.01 4290.6,7446.63
NetC63_1: C63.1 R94.2 U12.1 | length 295
  Top Layer w10: R94.2@4182.56,6949.01 4196.56,6963.01 4196.56,6990.77 C63.1@4182.93,7004.39 4196.56,7018.01 4196.56,7052.54 4219.72,7075.7 4258.45,7075.7 4308.22,7125.47 U12.1@4308.22,7158.03
NetC63_2: C63.2 R96.2 U12.2 | length 295.3
  Top Layer w10: R96.2@4230.56,6949.01 4216.56,6963.01 4216.56,6990.77 C63.2@4230.18,7004.39 4216.56,7018.01 4216.56,7044.26 4228,7055.7 4266.73,7055.7 4328.22,7117.18 4328.22,7125.47 ; U12.2@4327.9,7158.03 4327.9,7125.47 4328.06,7125.31
NetC65_1: C65.1 R99.2 U12.3 | length 246.5
  Top Layer w10: R99.2@4297.56,6949.01 4311.65,6963.1 4311.65,6991.24 C65.1@4298.49,7004.39 4312.12,7018.01 4312.12,7057.82 4347.84,7093.54 4347.84,7130.98 4348,7131.14 U12.3@4348,7163.7
NetC65_2: C65.2 R100.2 U12.4 | length 246.9
  Top Layer w10: R100.2@4345.74,6949.01 4331.65,6963.1 4331.65,6990.3 C65.2@4345.74,7004.39 4332.12,7018.01 4332.12,7049.53 4367.84,7085.26 4367.84,7130.98 4367.69,7131.14 U12.4@4367.69,7163.7
NetC66_1: C66.1 R101.2 U12.5 | length 246.9
  Top Layer w10: U12.5@4386.54,7163.7 4386.54,7131.14 4386.39,7130.98 4386.39,7085.26 4422.11,7049.53 4422.11,7018.01 C66.1@4408.49,7004.39 4422.58,6990.3 4422.58,6963.1 R101.2@4408.49,6949.01
NetC66_2: C66.2 R103.2 U12.6 | length 246.5
  Top Layer w10: U12.6@4406.23,7163.7 4406.23,7131.14 4406.39,7130.98 4406.39,7093.54 4442.11,7057.82 4442.11,7018.01 C66.2@4455.74,7004.39 4442.58,6991.24 4442.58,6963.1 R103.2@4456.67,6949.01
NetC67_1: C67.1 R104.2 U12.7 | length 295.3
  Top Layer w10: 4426.01,7125.47 4426.01,7117.18 4487.5,7055.7 4526.23,7055.7 4537.67,7044.26 4537.67,7018.01 C67.1@4524.05,7004.39 4537.67,6990.77 4537.67,6963.01 R104.2@4523.67,6949.01 ; 4426.17,7125.31 4426.33,7125.47 U12.7@4426.33,7158.03
NetC67_2: C67.2 R107.2 U12.8 | length 295
  Top Layer w10: U12.8@4446.01,7158.03 4446.01,7125.47 4495.78,7075.7 4534.51,7075.7 4557.67,7052.54 4557.67,7018.01 C67.2@4571.3,7004.39 4557.67,6990.77 4557.67,6963.01 R107.2@4571.67,6949.01
NetC68_1: C68.1 R111.2 U12.9 | length 211.1
  Top Layer w10: U12.9@4503.1,7215.11 4535.66,7215.11 4535.82,7214.96 4559.76,7214.96 4592.95,7181.77 4614.49,7181.77 C68.1@4628.11,7168.15 4641.74,7181.77 4669.87,7181.77 R111.2@4683.49,7168.15
NetC68_2: C68.2 R113.2 U12.10 | length 211.5
  Top Layer w10: U12.10@4503.1,7234.8 4535.66,7234.8 4535.82,7234.96 4568.04,7234.96 4601.23,7201.77 4614.49,7201.77 C68.2@4628.11,7215.39 4641.74,7201.77 4668.93,7201.77 R113.2@4683.49,7216.33
NetC69_1: C69.1 C70.1 R115.2 U12.27 | length 227
  Top Layer w10: U12.27@4251.13,7313.54 4251.23,7313.63 v2(4302.53,7313.63)
  Bottom Layer w20: R115.2@4188.91,7382.63 4189.11,7382.43 C69.1@4189.11,7325.51 4189.27,7325.35 C70.1@4251.13,7325.35 4290.81,7325.35 v2(4302.53,7313.63)
NetC71_1: C71.1 R116.2 U12.11 | length 211.5
  Top Layer w10: U12.11@4503.1,7254.48 4535.66,7254.48 4535.82,7254.33 4568.04,7254.33 4601.23,7287.51 4614.49,7287.51 C71.1@4628.11,7273.89 4641.74,7287.51 4668.93,7287.51 R116.2@4683.49,7272.95
NetC71_2: C71.2 R117.2 U12.12 | length 211.1
  Top Layer w10: U12.12@4503.1,7274.17 4535.66,7274.17 4535.82,7274.33 4559.76,7274.33 4592.95,7307.51 4614.49,7307.51 C71.2@4628.11,7321.13 4641.74,7307.51 4669.87,7307.51 R117.2@4683.49,7321.13
NetC73_1: C73.1 C74.1 R118.1 U12.26 | length 264.8
  Top Layer w10: 4204.94,7333.22 U12.26@4251.13,7333.22
  Top Layer w15: 4170.26,7354.37 4191.41,7333.22 4204.94,7333.22
  Top Layer w20: R118.1@4012.11,7395.39 4017.99,7389.52 C74.1@4069.11,7389.52 C73.1@4135.11,7389.52 4170.26,7354.37
NetC75_2: C75.2 C76.2 R119.2 U12.15 | length 229.3
  Top Layer w10: v2(4451.8,7333.22) U12.15@4503.1,7333.22
  Bottom Layer w20: v2(4451.8,7333.22) 4463.61,7345.04 C76.2@4503.1,7345.04 4564.64,7345.04 C75.2@4565.11,7345.51 4624.03,7345.51 R119.2@4624.53,7345.01
NetC77_1: C77.1 C78.1 R120.2 U12.14 | length 298.1
  Top Layer w10: U12.14@4503.1,7313.54 4542.43,7313.54
  Top Layer w15: 4542.43,7313.54 4562.43,7313.54 4581.53,7332.63
  Top Layer w20: 4581.53,7332.63 4639.62,7390.72 C78.1@4639.62,7392.01 C77.1@4639.62,7461.01 4639.62,7519.14 R120.2@4640.49,7520.01
NetC81_1: C81.1 R121.2 U16.29 | length 211.1
  Top Layer w10: R121.2@10712.44,7320.82 10726.06,7307.2 10754.19,7307.2 C81.1@10767.82,7320.82 10781.44,7307.2 10802.99,7307.2 10836.17,7274.01 10860.12,7274.01 10860.27,7273.85 U16.29@10892.83,7273.85
NetC81_2: C81.2 R122.2 U16.30 | length 211.5
  Top Layer w10: R122.2@10712.44,7272.64 10727,7287.2 10754.19,7287.2 C81.2@10767.82,7273.57 10781.44,7287.2 10794.7,7287.2 10827.89,7254.01 10860.11,7254.01 10860.27,7254.17 U16.30@10892.83,7254.17
NetC82_1: C82.1 R123.2 U16.31 | length 211.5
  Top Layer w10: R123.2@10712.44,7216.02 10727,7201.46 10754.19,7201.46 C82.1@10767.82,7215.08 10781.44,7201.46 10794.7,7201.46 10827.89,7234.64 10860.11,7234.64 10860.27,7234.48 U16.31@10892.83,7234.48
NetC82_2: C82.2 R124.2 U16.32 | length 211.1
  Top Layer w10: R124.2@10712.44,7167.84 10726.06,7181.46 10754.19,7181.46 C82.2@10767.82,7167.83 10781.44,7181.46 10802.99,7181.46 10836.17,7214.64 10860.12,7214.64 10860.27,7214.8 U16.32@10892.83,7214.8
NetC83_2: C83.2 U16.24 | length 79.7
  Top Layer w10: 10932.3,7446.32 10949.92,7428.7 U16.24@10949.92,7409.68
  Top Layer w15: C83.2@10905.82,7468.7 10909.92,7468.7 10932.3,7446.32
NetC84_1: C84.1 R125.2 U16.1 | length 295
  Top Layer w10: R125.2@10824.26,6948.7 10838.26,6962.7 10838.26,6990.45 C84.1@10824.63,7004.08 10838.26,7017.7 10838.26,7052.23 10861.42,7075.39 10900.15,7075.39 10949.92,7125.15 U16.1@10949.92,7157.71
NetC84_2: C84.2 R127.2 U16.2 | length 295.3
  Top Layer w10: R127.2@10872.26,6948.7 10858.26,6962.7 10858.26,6990.45 C84.2@10871.88,7004.08 10858.26,7017.7 10858.26,7043.94 10869.7,7055.39 10908.43,7055.39 10969.92,7116.87 10969.92,7125.15 ; U16.2@10969.6,7157.71 10969.6,7125.15 10969.76,7125
NetC86_1: C86.1 R130.2 U16.3 | length 246.5
  Top Layer w10: R130.2@10939.26,6948.7 10953.35,6962.79 10953.35,6990.92 C86.1@10940.19,7004.08 10953.82,7017.7 10953.82,7057.5 10989.54,7093.23 10989.54,7130.67 10989.7,7130.83 U16.3@10989.7,7163.39
NetC86_2: C86.2 R131.2 U16.4 | length 246.9
  Top Layer w10: R131.2@10987.44,6948.7 10973.35,6962.79 10973.35,6989.98 C86.2@10987.44,7004.08 10973.82,7017.7 10973.82,7049.22 11009.54,7084.94 11009.54,7130.67 11009.39,7130.83 U16.4@11009.39,7163.39
NetC87_1: C87.1 R132.2 U16.5 | length 246.9
  Top Layer w10: U16.5@11028.25,7163.39 11028.25,7130.83 11028.09,7130.67 11028.09,7084.94 11063.82,7049.22 11063.82,7017.7 C87.1@11050.19,7004.08 11064.28,6989.98 11064.28,6962.79 R132.2@11050.19,6948.7
NetC87_2: C87.2 R134.2 U16.6 | length 246.5
  Top Layer w10: U16.6@11047.93,7163.39 11047.93,7130.83 11048.09,7130.67 11048.09,7093.23 11083.82,7057.5 11083.82,7017.7 C87.2@11097.44,7004.08 11084.28,6990.92 11084.28,6962.79 R134.2@11098.37,6948.7
NetC88_1: C88.1 R135.2 U16.7 | length 295.3
  Top Layer w10: 11067.71,7125.15 11067.71,7116.87 11129.2,7055.39 11167.93,7055.39 11179.37,7043.94 11179.37,7017.7 C88.1@11165.75,7004.08 11179.37,6990.45 11179.37,6962.7 R135.2@11165.37,6948.7 ; 11067.87,7125 11068.03,7125.15 U16.7@11068.03,7157.71
NetC88_2: C88.2 R138.2 U16.8 | length 295
  Top Layer w10: U16.8@11087.71,7157.71 11087.71,7125.15 11137.48,7075.39 11176.21,7075.39 11199.37,7052.23 11199.37,7017.7 C88.2@11213,7004.08 11199.37,6990.45 11199.37,6962.7 R138.2@11213.37,6948.7
NetC89_1: C89.1 R142.2 U16.9 | length 211.1
  Top Layer w10: U16.9@11144.8,7214.8 11177.36,7214.8 11177.52,7214.64 11201.46,7214.64 11234.65,7181.46 11256.19,7181.46 C89.1@11269.82,7167.83 11283.44,7181.46 11311.57,7181.46 R142.2@11325.19,7167.83
NetC89_2: C89.2 R144.2 U16.10 | length 211.5
  Top Layer w10: U16.10@11144.8,7234.48 11177.36,7234.48 11177.52,7234.64 11209.75,7234.64 11242.93,7201.46 11256.19,7201.46 C89.2@11269.82,7215.08 11283.44,7201.46 11310.63,7201.46 R144.2@11325.19,7216.02
NetC90_1: C90.1 C91.1 R146.2 U16.27 | length 221.1
  Top Layer w10: U16.27@10892.83,7313.22 10938.22,7313.22 v2(10944,7319)
  Bottom Layer w20: R146.2@10830.61,7382.32 R146.2@10830.82,7382.11 C90.1@10830.82,7325.19 10830.97,7325.04 C91.1@10892.83,7325.04 10898.87,7319 v2@10938.55,7319
NetC92_1: C92.1 R147.2 U16.11 | length 211.5
  Top Layer w10: U16.11@11144.8,7254.17 11177.36,7254.17 11177.52,7254.01 11209.75,7254.01 11242.93,7287.2 11256.19,7287.2 C92.1@11269.82,7273.58 11283.44,7287.2 11310.63,7287.2 R147.2@11325.19,7272.64
NetC92_2: C92.2 R148.2 U16.12 | length 211.1
  Top Layer w10: U16.12@11144.8,7273.85 11177.36,7273.85 11177.52,7274.01 11201.46,7274.01 11234.65,7307.2 11256.19,7307.2 C92.2@11269.82,7320.82 11283.44,7307.2 11311.57,7307.2 R148.2@11325.19,7320.82
NetC94_1: C94.1 C95.1 R149.1 U16.26 | length 264.8
  Top Layer w10: 10846.64,7332.91 U16.26@10892.83,7332.91
  Top Layer w15: 10811.96,7354.05 10833.11,7332.91 10846.64,7332.91
  Top Layer w20: R149.1@10653.82,7395.08 10659.69,7389.2 C95.1@10710.82,7389.2 C94.1@10776.82,7389.2 10811.96,7354.05
NetC96_2: C96.2 C97.2 R150.2 U16.15 | length 229.3
  Top Layer w10: v2(11093.5,7332.91) U16.15@11144.8,7332.91
  Bottom Layer w20: v2(11093.5,7332.91) 11105.31,7344.72 C97.2@11144.8,7344.72 11206.34,7344.72 C96.2@11206.82,7345.19 11265.73,7345.19 R150.2@11266.23,7344.7
NetC98_1: C98.1 C99.1 R151.2 U16.14 | length 298.1
  Top Layer w10: U16.14@11144.8,7313.22 11184.13,7313.22
  Top Layer w15: 11184.13,7313.22 11204.13,7313.22 11223.23,7332.32
  Top Layer w20: 11223.23,7332.32 11281.32,7390.41 C99.1@11281.32,7391.7 C98.1@11281.32,7460.7 11281.32,7518.82 R151.2@11282.19,7519.7
NetC102_1: C102.1 R201.2 R202.2 U20.1 | length 196.7
  Top Layer w20: U20.1@3123.89,7745.8 3160.9,7745.8 3172.52,7734.18 R202.2@3172.52,7590.93
NetC104_1: C104.1 C106.1 C107.1 U21.11 | length 85.2
  Top Layer w10: 2050.2,6822.46 U21.11@2078.88,6822.46
  Top Layer w15: C104.1@1999,6809.63 2011.83,6822.46 2050.2,6822.46
NetC104_2: C104.2 C106.2 C107.2 L6.1 U21.8 | length 82.7
  Top Layer w10: 2052,6881.51 U21.8@2078.88,6881.51
  Top Layer w15: C104.2@1999,6888.37 2005.86,6881.51 2052,6881.51
NetC108_1: C108.1 R205.1 U22.3
NetC112_1: C112.1 D10.1 L3.1 Q5.1 Q5.2 Q5.3 U23.20 | length 100.2
  Top Layer w12: C112.1@723.94,6980.7 726.35,6978.3 726.06,6978.3 726.06,6882.19 U23.20@726.35,6881.91
NetC112_2: C112.2 U23.18 | length 99.8
  Top Layer w12: U23.18@777.53,6881.91 777.81,6882.19 777.81,6979.17 777.53,6979.17 C112.2@779.06,6980.7
NetC115_1: C115.1 C120.1 U23.9 | length 222.8
  Top Layer w12: U23.9@931.07,6657.5 931.07,6615.33 952.85,6593.55
  Top Layer w15: 952.85,6593.55 998.06,6548.34 C115.1@998.06,6522.7 998.06,6465.81 C120.1@995.71,6463.46
NetC115_2: C115.2 R212.1 R213.2 R214.1 U23.8 | length 428.8
  Top Layer w12: U23.8@905.48,6657.5 905.48,6592.29 918.54,6579.24
  Top Layer w15: 918.54,6579.24 942.94,6554.83 C115.2@942.94,6522.7 942.94,6468.22 R212.1@947.71,6463.46 894.5,6410.25 R213.2@894.5,6345.7 R214.1@972.01,6345.7
NetC116_1: C116.1 U23.7 | length 137.2
  Top Layer w12: U23.7@879.89,6657.5 879.89,6530.37 C116.1@887,6523.26
NetC117_1: C117.1 U23.5 | length 138
  Top Layer w12: C117.1@820.5,6523.26 828.71,6531.46 828.99,6531.46 828.99,6657.21 U23.5@828.71,6657.5
NetC118_1: C118.1 U23.17 | length 172.6
  Top Layer w12: C118.1@789.5,7043.14 789.5,7041.04 810,7020.54 810,6951.7 803.12,6944.82 U23.17@803.12,6881.91
NetC119_1: C119.1 U23.16 | length 165.7
  Top Layer w12: U23.16@828.71,6881.91 829.87,6883.07 829.87,7033.51 C119.1@839.5,7043.14
NetC120_2: C120.2 R212.2 | length 48
  Top Layer w15: R212.2@947.71,6408.34 C120.2@995.71,6408.34
NetC122_Ch1_2: C122_Ch1.2 R220_Ch1.2 U24_Ch1.5 | length 161.3
  Bottom Layer w15: R220_Ch1.2@1822,3702.18 C122_Ch1.2@1871,3702.18 1890.06,3683.11 1936.11,3683.11 1947.59,3694.59 U24_Ch1.5@1947.59,3717.62
NetC122_Ch2_2: C122_Ch2.2 R220_Ch2.2 U24_Ch2.5 | length 161.3
  Bottom Layer w15: R220_Ch2.2@3384,3702.1 C122_Ch2.2@3433,3702.1 3452.06,3683.04 3498.11,3683.04 3509.59,3694.51 U24_Ch2.5@3509.59,3717.54
NetC122_Ch3_2: C122_Ch3.2 R220_Ch3.2 U24_Ch3.5 | length 161.3
  Bottom Layer w15: R220_Ch3.2@4946,3702.02 C122_Ch3.2@4995,3702.02 5014.06,3682.96 5060.11,3682.96 5071.59,3694.43 U24_Ch3.5@5071.59,3717.46
NetC122_Ch4_2: C122_Ch4.2 R220_Ch4.2 U24_Ch4.5 | length 161.3
  Bottom Layer w15: R220_Ch4.2@6508,3701.94 C122_Ch4.2@6557,3701.94 6576.06,3682.88 6622.11,3682.88 6633.59,3694.36 U24_Ch4.5@6633.59,3717.38
NetC122_Ch5_2: C122_Ch5.2 R220_Ch5.2 U24_Ch5.5 | length 161.3
  Bottom Layer w15: R220_Ch5.2@8463.7,3701.86 C122_Ch5.2@8512.7,3701.86 8531.77,3682.8 8577.81,3682.8 8589.29,3694.28 U24_Ch5.5@8589.29,3717.3
NetC122_Ch6_2: C122_Ch6.2 R220_Ch6.2 U24_Ch6.5 | length 161.3
  Bottom Layer w15: R220_Ch6.2@10025.7,3701.79 C122_Ch6.2@10074.7,3701.79 10093.77,3682.72 10139.81,3682.72 10151.29,3694.2 U24_Ch6.5@10151.29,3717.23
NetC122_Ch7_2: C122_Ch7.2 R220_Ch7.2 U24_Ch7.5 | length 161.3
  Bottom Layer w15: R220_Ch7.2@11587.7,3701.71 C122_Ch7.2@11636.7,3701.71 11655.77,3682.64 11701.81,3682.64 11713.29,3694.12 U24_Ch7.5@11713.29,3717.15
NetC122_Ch8_2: C122_Ch8.2 R220_Ch8.2 U24_Ch8.5 | length 161.3
  Bottom Layer w15: R220_Ch8.2@13149.7,3701.63 C122_Ch8.2@13198.7,3701.63 13217.77,3682.56 13263.81,3682.56 13275.29,3694.04 U24_Ch8.5@13275.29,3717.07
NetC127_2: C127.2 U15.5 | length 62.9
  Top Layer w20: C127.2@4872.33,7667.98 4872.97,7668.61 U15.5@4934.93,7668.61
NetC128_2: C128.2 U19.5 | length 62.9
  Top Layer w20: C128.2@11514.01,7667.68 11514.67,7668.3 U19.5@11576.63,7668.3
NetC132_1: C132.1 U8.4 | length 64.7
  Top Layer w20: U8.4@2554.13,7082.3 2554.13,7018.06 C132.1@2554.5,7017.7
NetC135_Ch1_1: C135_Ch1.1 R159_Ch1.1 U29_Ch1.16 | length 104.7
  Bottom Layer w15: R159_Ch1.1@1576,5167.38 1576.06,5167.44 C135_Ch1.1@1629.36,5167.44 1630.01,5166.8 U29_Ch1.16@1680.43,5166.8
NetC135_Ch2_1: C135_Ch2.1 R159_Ch2.1 U29_Ch2.16 | length 104.7
  Bottom Layer w15: R159_Ch2.1@3138,5167.3 3138.06,5167.36 C135_Ch2.1@3191.36,5167.36 3192.01,5166.72 U29_Ch2.16@3242.43,5166.72
NetC135_Ch3_1: C135_Ch3.1 R159_Ch3.1 U29_Ch3.16 | length 104.7
  Bottom Layer w15: R159_Ch3.1@4700,5167.22 R159_Ch3.1@4700,5167.22 C135_Ch3.1@4753.36,5167.28 4754.01,5166.64 U29_Ch3.16@4804.43,5166.64
NetC135_Ch4_1: C135_Ch4.1 R159_Ch4.1 U29_Ch4.16 | length 104.7
  Bottom Layer w15: R159_Ch4.1@6262,5167.14 6262.06,5167.2 C135_Ch4.1@6315.36,5167.2 6316.01,5166.56 U29_Ch4.16@6366.43,5166.56
NetC135_Ch5_1: C135_Ch5.1 R159_Ch5.1 U29_Ch5.16 | length 104.7
  Bottom Layer w15: R159_Ch5.1@8217.7,5167.06 8217.76,5167.13 C135_Ch5.1@8271.06,5167.13 8271.71,5166.48 U29_Ch5.16@8322.13,5166.48
NetC135_Ch6_1: C135_Ch6.1 R159_Ch6.1 U29_Ch6.16 | length 104.7
  Bottom Layer w15: R159_Ch6.1@9779.7,5166.98 9779.76,5167.05 C135_Ch6.1@9833.06,5167.05 9833.71,5166.4 U29_Ch6.16@9884.13,5166.4
NetC135_Ch7_1: C135_Ch7.1 R159_Ch7.1 U29_Ch7.16 | length 104.7
  Bottom Layer w15: R159_Ch7.1@11341.7,5166.91 R159_Ch7.1@11341.7,5166.91 C135_Ch7.1@11395.06,5166.97 11395.71,5166.32 U29_Ch7.16@11446.13,5166.32
NetC135_Ch8_1: C135_Ch8.1 R159_Ch8.1 U29_Ch8.16 | length 104.7
  Bottom Layer w15: R159_Ch8.1@12903.7,5166.83 R159_Ch8.1@12903.7,5166.83 C135_Ch8.1@12957.06,5166.89 12957.71,5166.24 U29_Ch8.16@13008.13,5166.24
NetC138_1: C138.1 C139.1 R163.2 U25.1 U25.3 | length 165.2
  Top Layer w20: U25.3@3191.4,8016.6 3232.6,8016.6 3243,8027 3243,8080 3231.6,8091.4 U25.1@3191.4,8091.4
NetC141_1: C141.1 R176.1 U31.3
NetC142_1: C142.1 R188.2 R190.1 U22.1 | length 293.4
  Top Layer w15: U22.1@2019.58,7647.23 2019.58,7663.09 2043.5,7687 v2(2067,7687)
  Bottom Layer w15: R188.2@1950.62,7673 1951.5,7672.13 R190.1@1951.5,7614 1952.69,7615.2 C142.1@2021,7615.2 2067,7661.2 v2(2067,7687)
NetC143_1: C143.1 R189.2 R191.1 U31.1 | length 273.7
  Top Layer w15: U31.1@2019.08,7943.42 2034.94,7943.42 2061,7917.35 v2(2061,7917)
  Bottom Layer w15: R189.2@1980.62,7883 1981.5,7883.87 C143.1@1981.5,7943.58 ; R191.1@1982,8012.5 1981.5,8012 C143.1@1981.5,7943.58 ; v2(2061,7917) 2034.42,7943.58 C143.1@1981.5,7943.58
NetC144_1: C144.1 R177.1 U15.3 | length 211.8
  Top Layer w20: U15.3@5009.73,7560.35 5010.39,7561 C144.1@5096.5,7561 5096,7561.5 R177.1@5096,7685.5
NetC145_1: C145.1 R181.1 U19.3 | length 210.1
  Top Layer w20: U19.3@11652.47,7560.31 C145.1@11738.58,7560.31 ; C145.1@11738.08,7560.81 R181.1@11738.08,7684.81
NetC146_1: C146.1 R194.2 R202.1 U20.3 | length 234.1
  Top Layer w20: R194.2@3040.5,7523.7 C146.1@3040.5,7591 3040.56,7590.93 R202.1@3109.53,7590.93 3100,7600.46 3100,7653.7 3117.3,7671 U20.3@3123.89,7671
NetC147_1: C147.1 R184.1 U7.3 | length 196.4
  Top Layer w20: U7.3@2554.6,7639.52 2554.6,7730.28 C147.1@2553.5,7731.39 2657.44,7731.39 R184.1@2657.5,7731.32
NetC148_1: C148.1 R98.1 Y1.1 | length 147.2
  Top Layer w20: R98.1@4178.38,7821.11 4179,7820.49 C148.1@4179,7749 4179.32,7749.32 Y1.1@4253.71,7749.32
NetC149_1: C149.1 R129.1 Y2.1 | length 228.4
  Top Layer w20: R129.1@10819.08,7821.8 10819.7,7821.18 10819.7,7749.69 C149.1@10820.02,7750 ; R129.1@10819.5,7831 10820.02,7830.48 C149.1@10820.02,7750 ; Y2.1@10894.41,7750 C149.1@10820.02,7750
NetC151_Ch1_2: C151_Ch1.2 R193_Ch1.2 U29_Ch1.7 | length 125.4
  Bottom Layer w15: U29_Ch1.7@1833.98,5391.2 1833.98,5422.61 1846.98,5435.62 C151_Ch1.2@1846.98,5462 1895.62,5462 R193_Ch1.2@1896,5462.38
NetC151_Ch2_2: C151_Ch2.2 R193_Ch2.2 U29_Ch2.7 | length 125.4
  Bottom Layer w15: U29_Ch2.7@3395.98,5391.13 3395.98,5422.54 3408.98,5435.54 C151_Ch2.2@3408.98,5461.92 3457.62,5461.92 R193_Ch2.2@3458,5462.3
NetC151_Ch3_2: C151_Ch3.2 R193_Ch3.2 U29_Ch3.7 | length 125.4
  Bottom Layer w15: U29_Ch3.7@4957.98,5391.05 4957.98,5422.46 4970.98,5435.46 C151_Ch3.2@4970.98,5461.84 5019.62,5461.84 R193_Ch3.2@5020,5462.22
NetC151_Ch4_2: C151_Ch4.2 R193_Ch4.2 U29_Ch4.7 | length 125.4
  Bottom Layer w15: U29_Ch4.7@6519.98,5390.97 6519.98,5422.38 6532.98,5435.39 C151_Ch4.2@6532.98,5461.76 6581.62,5461.76 R193_Ch4.2@6582,5462.14
NetC151_Ch5_2: C151_Ch5.2 R193_Ch5.2 U29_Ch5.7 | length 125.4
  Bottom Layer w15: U29_Ch5.7@8475.68,5390.89 8475.68,5422.3 8488.69,5435.31 C151_Ch5.2@8488.69,5461.69 R193_Ch5.2@8537.32,5461.69 R193_Ch5.2@8537.7,5462.06
NetC151_Ch6_2: C151_Ch6.2 R193_Ch6.2 U29_Ch6.7 | length 125.4
  Bottom Layer w15: U29_Ch6.7@10037.68,5390.81 10037.68,5422.22 10050.69,5435.23 C151_Ch6.2@10050.69,5461.61 10099.32,5461.61 R193_Ch6.2@10099.7,5461.98
NetC151_Ch7_2: C151_Ch7.2 R193_Ch7.2 U29_Ch7.7 | length 125.4
  Bottom Layer w15: U29_Ch7.7@11599.68,5390.73 11599.68,5422.14 11612.69,5435.15 C151_Ch7.2@11612.69,5461.53 11661.32,5461.53 R193_Ch7.2@11661.7,5461.91
NetC151_Ch8_2: C151_Ch8.2 R193_Ch8.2 U29_Ch8.7 | length 125.4
  Bottom Layer w15: U29_Ch8.7@13161.68,5390.65 13161.68,5422.06 13174.69,5435.07 C151_Ch8.2@13174.69,5461.45 13223.32,5461.45 R193_Ch8.2@13223.7,5461.83
NetC152_1: C152.1 C153.1 C154.1 C155.1 C156.1 L5.2 R195.1 U21.12 | length 289.6
  Top Layer w10: 2059,6777 2059,6798 2063.77,6802.77 U21.12@2078.88,6802.77 2078.88,6743.74 C155.1@2074.25,6739.11
  Bottom Layer w20: v1(2032,6721) 2157.9,6721 2158.2,6720.7 R195.1@2197,6759.5
NetC159_2: C159.2 U21.6 | length 69.1
  Top Layer w10: U21.6@2189.12,6901.2 2189.12,6929
  Top Layer w15: 2189.12,6929 2189.12,6953.5 C159.2@2201,6965.38
NetC164_1: C164.1 R198.2 U21.1 | length 125.2
  Top Layer w10: U21.1@2189.12,6802.77 2204.23,6802.77 2214,6793
  Top Layer w15: 2214,6793 2226.38,6780.62 C164.1@2254,6780.62 2304.76,6780.62 R198.2@2305,6780.38
NetC165_1: C165.1 U25.4 | length 66.7
  Top Layer w20: C165.1@3299.5,7950 3299.66,7950.17 U25.4@3299.66,8016.6
NetD3_Ch1_2: D3_Ch1.2 R19_Ch1.1 | length 66.6
  Top Layer w15: D3_Ch1.2@1834.11,3396.46 1889.32,3396.46 R19_Ch1.1@1897.37,3388.42
NetD3_Ch2_2: D3_Ch2.2 R19_Ch2.1 | length 66.6
  Top Layer w15: D3_Ch2.2@3396.11,3396.38 3451.32,3396.38 R19_Ch2.1@3459.37,3388.34
NetD3_Ch3_2: D3_Ch3.2 R19_Ch3.1 | length 66.6
  Top Layer w15: D3_Ch3.2@4958.11,3396.3 5013.32,3396.3 R19_Ch3.1@5021.37,3388.26
NetD3_Ch4_2: D3_Ch4.2 R19_Ch4.1 | length 66.6
  Top Layer w15: D3_Ch4.2@6520.11,3396.22 6575.32,3396.22 R19_Ch4.1@6583.37,3388.18
NetD3_Ch5_2: D3_Ch5.2 R19_Ch5.1 | length 66.6
  Top Layer w15: D3_Ch5.2@8475.81,3396.15 8531.03,3396.15 R19_Ch5.1@8539.07,3388.1
NetD3_Ch6_2: D3_Ch6.2 R19_Ch6.1 | length 66.6
  Top Layer w15: D3_Ch6.2@10037.81,3396.07 10093.03,3396.07 R19_Ch6.1@10101.07,3388.02
NetD3_Ch7_2: D3_Ch7.2 R19_Ch7.1 | length 66.6
  Top Layer w15: D3_Ch7.2@11599.81,3395.99 11655.03,3395.99 R19_Ch7.1@11663.07,3387.94
NetD3_Ch8_2: D3_Ch8.2 R19_Ch8.1 | length 66.6
  Top Layer w15: D3_Ch8.2@13161.81,3395.91 13217.03,3395.91 R19_Ch8.1@13225.07,3387.86
NetD4_Ch1_2: D4_Ch1.2 R25_Ch1.1 | length 70.3
  Top Layer w15: R25_Ch1.1@1690.83,3390.59 1697.11,3396.87 1697.11,3450.77 D4_Ch1.2@1702.46,3456.11
NetD4_Ch2_2: D4_Ch2.2 R25_Ch2.1 | length 70.3
  Top Layer w15: R25_Ch2.1@3252.83,3390.51 3259.11,3396.79 3259.11,3450.69 D4_Ch2.2@3264.46,3456.04
NetD4_Ch3_2: D4_Ch3.2 R25_Ch3.1 | length 70.3
  Top Layer w15: R25_Ch3.1@4814.83,3390.43 4821.11,3396.71 4821.11,3450.61 D4_Ch3.2@4826.46,3455.96
NetD4_Ch4_2: D4_Ch4.2 R25_Ch4.1 | length 70.3
  Top Layer w15: R25_Ch4.1@6376.83,3390.35 6383.11,3396.64 6383.11,3450.53 D4_Ch4.2@6388.46,3455.88
NetD4_Ch5_2: D4_Ch5.2 R25_Ch5.1 | length 70.3
  Top Layer w15: R25_Ch5.1@8332.53,3390.27 8338.81,3396.56 8338.81,3450.45 D4_Ch5.2@8344.16,3455.8
NetD4_Ch6_2: D4_Ch6.2 R25_Ch6.1 | length 70.3
  Top Layer w15: R25_Ch6.1@9894.53,3390.19 9900.81,3396.48 9900.81,3450.37 D4_Ch6.2@9906.16,3455.73
NetD4_Ch7_2: D4_Ch7.2 R25_Ch7.1 | length 70.3
  Top Layer w15: R25_Ch7.1@11456.53,3390.12 11462.81,3396.4 11462.81,3450.3 D4_Ch7.2@11468.16,3455.65
NetD4_Ch8_2: D4_Ch8.2 R25_Ch8.1 | length 70.3
  Top Layer w15: R25_Ch8.1@13018.53,3390.04 13024.81,3396.32 13024.81,3450.22 D4_Ch8.2@13030.16,3455.57
NetD5_1: D5.1 Q4.1 R81.2 | length 92.2
  Top Layer w20: v1(574,1695) 620.05,1695 Q4.1@620.09,1694.96
  Bottom Layer w20: v1(574,1695) 574.04,1694.96 R81.2@620.09,1694.96
NetD5_2: D5.2 Q2.1 Q2.2 Q2.3 Q3.1 Q3.2 Q3.3 Q4.2
  other v1: 83,1718 223,1718 363,1718 503,1718 83,1788 223,1788 363,1788 503,1788 83,1858 223,1858 363,1858 503,1858 83,1928 223,1928 363,1928 503,1928 83,1998 223,1998 363,1998 503,1998
NetD6_1: D6.1 R80.1 U11.10 | length 156.5
  Top Layer w10: 934,1537.11 945.89,1537.11 968,1515 985.96,1515 U11.10@985.96,1544.48 985.96,1591.04 977.88,1599.12 970,1599.12
NetD6_2: D6.2 Q2.4 Q3.4 Q4.3 R80.2 | length 544.4
  Top Layer w35: v1(527.44,1465.56) v1(573.44,1465.56) Q3.4@611.33,1465.56
  Bottom Layer w35: v1(527.44,1465.56) v1(573.44,1465.56) 692.89,1465.56 721,1493.67 v1(721,1702) v1(721,1749)
NetD7_1: D7.1 R87.2 U11.2 | length 465.8
  Top Layer w10: 976,1439 996,1439 1005.65,1429.35 U11.2@1005.65,1383.07
  Top Layer w15: v1(1088.67,1326.5) R87.2@1127,1326.5
  Top Layer w20: 918.33,1434 923.33,1439 976,1439
  Bottom Layer w20: v1(824,1381) 870,1381 925,1326 v1@1089,1326
  other v1: 824,1434 877,1434
NetD9_2: D9.2 L3.2 Q6.5 Q6.6 Q6.7 Q6.8 Q6.9
  other v4: 721.5,7463.7 761.5,7463.7 801.5,7463.7 721.5,7503.7 761.5,7503.7 801.5,7503.7 721.5,7543.7 761.5,7543.7 801.5,7543.7 721.5,7583.7 761.5,7583.7 801.5,7583.7
NetD10_2: D10.2 R211.2 U23.12 | length 168.2
  Top Layer w12: U23.12@931.07,6881.91 931.07,6960.26 946.51,6975.7 R211.2@946.51,7043.7
NetD11_2: D11.2 R209.2 | length 79.4
  Top Layer w20: D11.2@817.5,7939.7 818.5,7938.7 R209.2@896.44,7938.7
NetD13_2: D13.2 R178.2 | length 55.5
  Top Layer w20: D13.2@2435.43,7319.88 D13.2@2433.99,7321.32 R178.2@2487.44,7321.32
NetD14_2: D14.2 R179.2 | length 65.8
  Top Layer w20: R179.2@3869.56,7805 3934.6,7805 D14.2@3935.11,7804.5
NetD15_2: D15.2 R180.2 | length 66.1
  Top Layer w20: R180.2@3480.12,7660 3545.5,7660 D15.2@3546,7659.5
NetD17_2: D17.2 R182.2 | length 58.9
  Top Layer w20: R182.2@2281.12,7710.56 D17.2@2340.06,7710.56
NetD18_2: D18.2 R183.2 | length 58.2
  Top Layer w20: R183.2@2480.56,8037 2537.91,8037 D18.2@2538.5,8037.6
NetD33_2: D33.2 R59.2 | length 62
  Top Layer w10: D33.2@7104.85,7969.5 7105,7969.35 R59.2@7105,7907.56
